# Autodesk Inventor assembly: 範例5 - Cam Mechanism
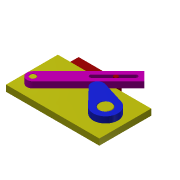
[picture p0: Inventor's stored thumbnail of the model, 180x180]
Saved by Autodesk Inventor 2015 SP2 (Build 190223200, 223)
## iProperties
Created: 2019-10
Part Number: 範例5 - Cam Mechanism
Document SubType Name: Assembly
Designer: Kuan_Lun Hsu
Mass: 4815.18 g
Surface Area: 4427.85 cm^2
Volume: 4815.18 cm^3
Density: 1 g/cm^3
Author: Kuan_Lun Hsu
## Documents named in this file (5)
- C:\Users\Kuan_Lun Hsu\Desktop\Topic 14 - Cam Mechanism(Stress Analysis)\Cam Mechanism(Stress Analysis).iam
- C:\Users\Kuan_Lun Hsu\Desktop\Topic 14 - Cam Mechanism(Stress Analysis)\Fixed Link.ipt
- C:\Users\Kuan_Lun Hsu\Desktop\Topic 14 - Cam Mechanism(Stress Analysis)\Slider.ipt
- C:\Users\Kuan_Lun Hsu\Desktop\Topic 14 - Cam Mechanism(Stress Analysis)\Cam.ipt
- C:\Users\Kuan_Lun Hsu\Desktop\Topic 14 - Cam Mechanism(Stress Analysis)\Follower.ipt
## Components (4 placed, 4 different names)
1. Fixed Link:1 — 貼合:1, 齊平:1, 插入:1, 插入:2, 角度:1
2. Slider:1 — 貼合:1, 齊平:1, 相切:2
3. Cam:1 — 插入:1, 相切:1
4. Follower:1 — 插入:2, 相切:1, 相切:2, 角度:1
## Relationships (7: Insert 2, Tangent 2, Mate 1, Flush 1, Angle 1)
- 貼合:1 [Mate]: Fixed Link:1 ↔ Slider:1
- 齊平:1 [Flush]: Fixed Link:1 ↔ Slider:1
- 插入:1 [Insert]: Fixed Link:1 ↔ Cam:1
- 插入:2 [Insert]: Fixed Link:1 ↔ Follower:1
- 相切:1 [Tangent]: Cam:1 ↔ Follower:1
- 相切:2 [Tangent]: Slider:1 ↔ Follower:1
- 角度:1 [Angle]: Fixed Link:1 ↔ Follower:1
